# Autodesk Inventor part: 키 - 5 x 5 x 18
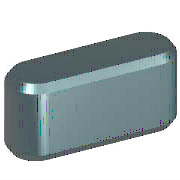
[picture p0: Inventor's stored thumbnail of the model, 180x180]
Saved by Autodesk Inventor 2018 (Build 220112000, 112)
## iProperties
Created: 2012-02
Part Number: 키 - 5 x 5 x 18
Material: 강철, 연강
Description: 키 및 해당 키홈
Document SubType Name: Modeling
Standard: KS B 1311
Designer: mduedu
Standards Organization: KS
Language: ko-KR
Size Designation: 5 x 5 x 18
Categories: <MemberInstance><Categories><Category DisplayName="샤프트 부품" InternalName="7f7aeb1f-a693-4053-b835-cee3144e0d98" Mnemonic="SHFT"><Category DisplayName="키" Interna
Density: 7.86 g/cm^3
Mass: 3.27476 g
Surface Area: 3.57848 cm^2
Volume: 0.416636 cm^3
Appearance: 노란색
IsCustomPart: 1
Author: mduedu
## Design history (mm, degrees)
workplane "Work Plane1"
workplane "Work Plane2"
sketch "스케치1"
  geometry: L1 (2.5, 2.5)-(15.5, 2.5); L2 (15.5, -2.5)-(2.5, -2.5); L3 (0, 9.4)-(0, -7.4) reference; L4 (-5, 0)-(30, 0) reference; L5 (18, 0)-(18, 7); A1 r 2.5 centre (2.5, 0) between (2.5, 2.5) and (2.5, -2.5); A2 r 2.5 centre (15.5, 0) between (15.5, -2.5) and (15.5, 2.5)
  constraints: 6 end point, 5 point on circle, 4 tangent, 3 point on line, 2 centre point, 1 horizontal, 1 parallel, 1 perpendicular
  dimensions: "d0" = 2.5 radius of A1 (= 0.5 x PB); "d13" = 2.5 radius of A2 (= 0.5 x PB); "d14" = 18 distance between parallel lines of L5 L3 (= NLG)
extrude "본체1" new body sketch "스케치1" taper "d3" = 0 deg; stored distance "d4" = 10
workplane "Work Plane3"
body "Solid1"
chamfer "모따기1" distance "d8" = 0.4 (= PHH); stored, may be unused: second distance "d9" = 0.4 (= PHH), angle "d15" = 45 deg
other parameters: "d1" = -3 (= -PNT), "d2" = 2 (= PH - PNT), "NLG" = 18 [user parameter; used in 3 equation terms], "PB" = 5 [user parameter; used in 2 equation terms], "PNT" = 3 [user parameter; used in 2 equation terms], "PH" = 5 [user parameter; used in 1 equation term], "PHH" = 0.4 [user parameter; used in 2 equation terms], "d10" = 0, "d16" = 0, "d17" = 0, "d18" = 0, "WDMIN" = 12 [user parameter], "PLB2" = 18 (= NLG) [user parameter], "WDMAX" = 17 [user parameter], "PLB1" = 18 (= NLG) [user parameter], "RR" = 0.16 [user parameter], "PUEB" = 2.3 [user parameter]
